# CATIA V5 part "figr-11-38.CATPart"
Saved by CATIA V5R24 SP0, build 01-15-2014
Part number: Part1
Bounding box of the stored display mesh (mm): x -177 to 59, y -180 to 60, z 0 to 80
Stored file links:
  D:\KAVITA\CATIA V5-6R2014 Project_ Kavita\CATIA V5-6R2014_partfiles\Partfiles\c11_catia_v5-6r2014_prt\figr-11-38.CATPart
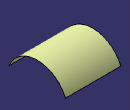
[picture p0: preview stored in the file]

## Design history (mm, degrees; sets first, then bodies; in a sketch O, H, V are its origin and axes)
Set1
  Extrude1: Element1 Sketch1, Lim1 59, Lim2 59, Direction yz-plane
  Scaling1: ToTransfor Extrude1, Reference vertex [face of Extrude1], Ratio 2
Body1 (main body)
  Sketch1 on yz-plane, origin (0, 0, 0), H (0, 1, 0), V (0, 0, 1)
    arc A1 centre (0, -25) radius 65 from (-60, 0) to (60, 0) cw
    point P2 (-60, 0)
    point P3 (60, 0)
    coincidence: P2 H, P3 H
